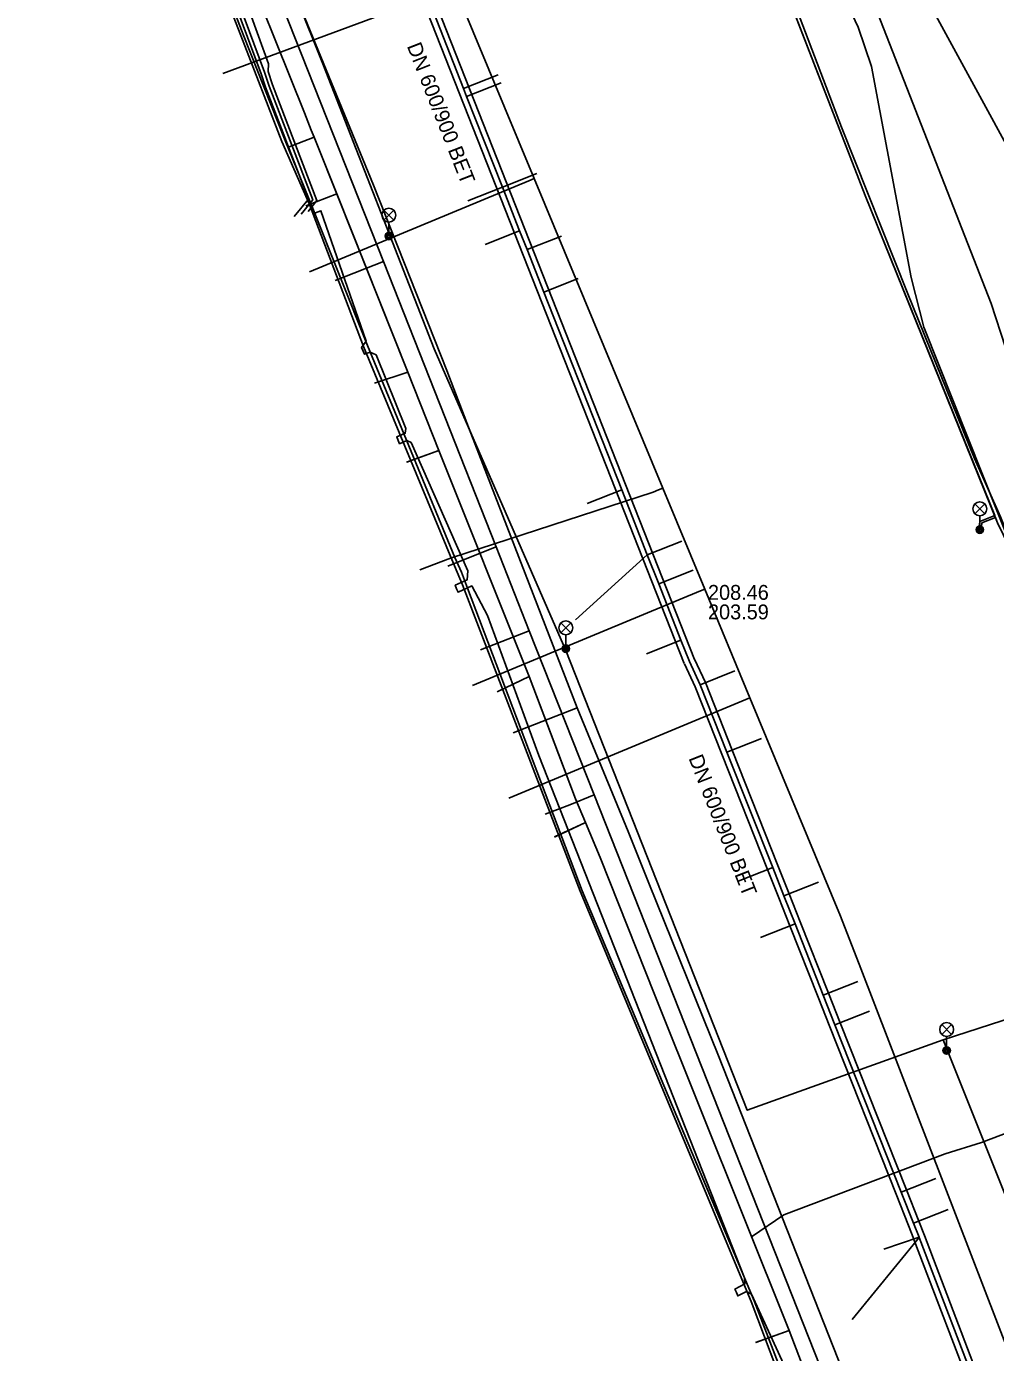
# Model space of a CAD drawing. Extents: x -595540 to -593988, y -1160850 to -1159202.
# Drawn here: x -595539.6 to -595487.4, y -1160398.9 to -1160327.6 of the extents above; entities that cross this region are included whole.
import ezdxf

# ---------------------------------------------------------------- set-up
doc = ezdxf.new("R2010")
doc.units = 0
for name, color, linetype in [('BKOM-ODVODNENI_trasa sítě', 7, 'Continuous'), ('BKOM_kabel koordinační_optický', 7, 'Continuous'), ('BVK-JEDNOTNA_popisy', 7, 'Continuous'), ('BVK-JEDNOTNA_trasa sítě', 7, 'Continuous'), ('BVK-JEDNOTNA_trasa sítě obvodem', 7, 'Continuous'), ('BVK-VODOVOD_trasa sítě', 7, 'Continuous'), ('CETIN_kabel podzemní', 7, 'Continuous'), ('DESTOVA_trasa neprovozované sítě', 7, 'Continuous'), ('DSP-SDEL-VODAFONE_kabel', 7, 'Continuous'), ('EON-NN_kabel', 7, 'Continuous'), ('EON-VN_kabel', 7, 'Continuous'), ('INNOGY-NTL_trasa sítě', 7, 'Continuous'), ('JEDNOTNA_trasa neprovozované sítě', 7, 'Continuous'), ('QUANTCOM_kabel', 7, 'Continuous'), ('TSB_kabel VO', 7, 'Continuous'), ('TSB_lampy VO', 7, 'Continuous')]:
    doc.layers.add(name, color=color, linetype=linetype)

msp = doc.modelspace()

# ---------------------------------------------------------------- linework, layer by layer
at = {"layer": 'BKOM-ODVODNENI_trasa sítě'}
msp.add_lwpolyline([(-595475.09, -1160355.55), (-595496.29, -1160316.63)], dxfattribs=at)
at = {"layer": 'BKOM_kabel koordinační_optický'}
msp.add_lwpolyline([(-595453.88, -1160433.69), (-595454.28, -1160431.7), (-595454.73, -1160428.35), (-595462.77, -1160409.14), (-595463.73, -1160407.01), (-595469.51, -1160393.32), (-595469.87, -1160391.31), (-595471.08, -1160389.95), (-595477.1, -1160376.11), (-595482.21, -1160364.84), (-595487.33, -1160354.29), (-595494.46, -1160336.67), (-595499.2, -1160324.44), (-595503.07, -1160314.66), (-595503, -1160311.72), (-595511.85, -1160289.79), (-595512.776, -1160289.263), (-595513.395, -1160289.497), (-595514.12, -1160290.65), (-595514.78, -1160289.19), (-595513.85, -1160288.56)], dxfattribs=at)
at = {"layer": 'BVK-JEDNOTNA_popisy'}
msp.add_line((-595502.914, -1160358.559), (-595502.914, -1160358.559), dxfattribs=at)
at = {"layer": 'BVK-JEDNOTNA_trasa sítě'}
for points in [[(-595503.914, -1160361.759), (-595504.369, -1160360.605), (-595505.564, -1160357.572), (-595506.18, -1160356.009), (-595507.555, -1160352.52), (-595511.753, -1160341.867), (-595512.651, -1160339.588), (-595513.047, -1160338.583), (-595513.975, -1160336.229), (-595515.904, -1160331.336), (-595516.073, -1160330.908), (-595517.51, -1160327.261), (-595518.002, -1160326.012), (-595520.106, -1160320.768)], [(-595488.167, -1160401.618), (-595491.55, -1160392.753), (-595491.553, -1160392.744), (-595491.851, -1160391.991), (-595492.518, -1160390.308), (-595496.082, -1160381.308), (-595496.715, -1160379.709), (-595498.232, -1160375.878), (-595498.828, -1160374.372), (-595499.432, -1160372.847), (-595501.895, -1160366.627), (-595503.331, -1160363.001), (-595503.914, -1160361.759)]]:
    msp.add_lwpolyline(points, dxfattribs=at)
at = {"layer": 'BVK-JEDNOTNA_trasa sítě obvodem'}
for points in [[(-595504.193, -1160361.869), (-595518.281, -1160326.123), (-595520.385, -1160320.88)], [(-595519.828, -1160320.656), (-595517.723, -1160325.901), (-595503.635, -1160361.649)], [(-595503.642, -1160361.632), (-595503.055, -1160362.882), (-595501.616, -1160366.517), (-595499.153, -1160372.737), (-595498.549, -1160374.262), (-595497.953, -1160375.768), (-595496.436, -1160379.599), (-595495.803, -1160381.198), (-595492.239, -1160390.198), (-595491.572, -1160391.88), (-595491.271, -1160392.641), (-595491.267, -1160392.652), (-595487.887, -1160401.511)], [(-595488.448, -1160401.724), (-595491.833, -1160392.854), (-595491.835, -1160392.847), (-595492.13, -1160392.101), (-595492.797, -1160390.419), (-595496.361, -1160381.418), (-595496.994, -1160379.819), (-595498.511, -1160375.988), (-595499.107, -1160374.482), (-595499.711, -1160372.957), (-595502.174, -1160366.737), (-595503.607, -1160363.12), (-595504.186, -1160361.886)]]:
    msp.add_lwpolyline(points, dxfattribs=at)
at = {"layer": 'BVK-VODOVOD_trasa sítě'}
for points in [[(-595420.455, -1160569.95), (-595424.738, -1160557.073), (-595431.327, -1160540.422), (-595434.589, -1160532.179), (-595436.214, -1160528.074), (-595442.962, -1160511.021), (-595456.206, -1160477.553), (-595459.57, -1160469.052), (-595464.421, -1160456.794), (-595465.595, -1160453.828), (-595470.116, -1160442.088), (-595472.995, -1160434.855), (-595482.155, -1160410.824), (-595494.687, -1160378.28), (-595495.79, -1160375.461), (-595500.663, -1160363.717), (-595503.091, -1160357.865), (-595505.35, -1160352.422), (-595512.262, -1160335.764), (-595517.983, -1160321.988), (-595525.805, -1160303.126), (-595529.181, -1160294.991), (-595529.357, -1160294.499)], [(-595512.262, -1160335.764), (-595512.546, -1160335.882), (-595524.354, -1160340.782)], [(-595505.35, -1160352.422), (-595505.582, -1160352.518), (-595505.858, -1160352.632), (-595516.77, -1160356.193), (-595518.424, -1160356.822)], [(-595503.091, -1160357.865), (-595503.313, -1160357.957), (-595515.592, -1160363.052)], [(-595500.663, -1160363.717), (-595501.094, -1160363.896), (-595513.633, -1160369.104)]]:
    msp.add_lwpolyline(points, dxfattribs=at)
at = {"layer": 'CETIN_kabel podzemní'}
for points in [[(-595535.44, -1160304.73), (-595532.73, -1160311.57), (-595528.44, -1160322.69), (-595524.63, -1160332.22), (-595524.26, -1160333.15), (-595524.11, -1160333.54)], [(-595530.4, -1160311.78), (-595527.16, -1160320.89), (-595520.91, -1160336.12), (-595516.97, -1160346.1), (-595515.89, -1160348.9), (-595509.95, -1160364.24)], [(-595524.11, -1160333.54), (-595523.89, -1160334.08), (-595522.89, -1160336.58)], [(-595522.89, -1160336.58), (-595524.56, -1160337.23)], [(-595522.89, -1160336.58), (-595519.06, -1160346.19)], [(-595519.06, -1160346.19), (-595520.8, -1160346.76)], [(-595519.06, -1160346.19), (-595517.4, -1160350.4)], [(-595517.4, -1160350.4), (-595519.12, -1160351.02)], [(-595517.4, -1160350.4), (-595512.53, -1160362.57)], [(-595512.53, -1160362.57), (-595514.26, -1160363.38)], [(-595512.53, -1160362.57), (-595510.96, -1160366.72)], [(-595509.95, -1160364.24), (-595513.39, -1160365.6)], [(-595509.95, -1160364.24), (-595507.21, -1160370.91), (-595506.09, -1160373.69), (-595502.35, -1160382.98), (-595492.49, -1160408.01)], [(-595510.96, -1160366.72), (-595510.05, -1160369.15), (-595509.51, -1160370.42)], [(-595509.51, -1160370.42), (-595511.18, -1160371.2)], [(-595509.51, -1160370.42), (-595508.72, -1160372.3), (-595505.77, -1160379.71), (-595498.55, -1160397.76)], [(-595498.55, -1160397.76), (-595500.34, -1160398.41)], [(-595498.55, -1160397.76), (-595494.66, -1160407.96)]]:
    msp.add_lwpolyline(points, dxfattribs=at)
at = {"layer": 'DESTOVA_trasa neprovozované sítě'}
for p, q in [((-595510.05, -1160359.51), (-595506.18, -1160356.009)), ((-595495.16, -1160397.17), (-595491.55, -1160392.753))]:
    msp.add_line(p, q, dxfattribs=at)
at = {"layer": 'DSP-SDEL-VODAFONE_kabel'}
msp.add_line((-595525.54, -1160334.09), (-595524.11, -1160333.54), dxfattribs=at)
for points in [[(-595435.305, -1160474.248), (-595440.905, -1160460.593), (-595441.624, -1160459.06), (-595443.903, -1160453.407), (-595444.463, -1160451.965), (-595447.439, -1160442.87), (-595449.5, -1160437.934), (-595451.793, -1160431.633), (-595454.837, -1160425.072), (-595456.717, -1160421.092), (-595460.193, -1160411.285), (-595468.387, -1160391.375), (-595474.605, -1160375.018), (-595475.298, -1160372.796), (-595476.233, -1160371.486), (-595479.459, -1160363.137), (-595482.711, -1160354.568), (-595483.438, -1160353.548), (-595486.91, -1160344.849), (-595487.674, -1160342.479), (-595505.065, -1160298.01)], [(-595435.305, -1160474.248), (-595440.905, -1160460.593), (-595441.624, -1160459.06), (-595443.903, -1160453.407), (-595444.463, -1160451.965), (-595447.439, -1160442.87), (-595449.5, -1160437.934), (-595451.793, -1160431.633), (-595454.837, -1160425.072), (-595456.717, -1160421.092), (-595460.193, -1160411.285), (-595468.387, -1160391.375), (-595474.605, -1160375.018), (-595475.298, -1160372.796), (-595476.233, -1160371.486), (-595479.459, -1160363.137), (-595482.711, -1160354.568), (-595483.438, -1160353.548), (-595486.91, -1160344.849), (-595487.674, -1160342.479), (-595505.065, -1160298.01)], [(-595435.305, -1160474.248), (-595440.905, -1160460.593), (-595441.624, -1160459.06), (-595443.903, -1160453.407), (-595444.463, -1160451.965), (-595447.439, -1160442.87), (-595449.5, -1160437.934), (-595451.793, -1160431.633), (-595454.837, -1160425.072), (-595456.717, -1160421.092), (-595460.193, -1160411.285), (-595468.387, -1160391.375), (-595474.605, -1160375.018), (-595475.298, -1160372.796), (-595476.233, -1160371.486), (-595479.459, -1160363.137), (-595482.711, -1160354.568), (-595483.438, -1160353.548), (-595486.91, -1160344.849), (-595487.674, -1160342.479), (-595505.065, -1160298.01)], [(-595535.44, -1160304.73), (-595532.73, -1160311.57), (-595528.44, -1160322.69), (-595524.63, -1160332.22), (-595524.26, -1160333.15), (-595524.11, -1160333.54)], [(-595524.11, -1160333.54), (-595523.89, -1160334.08), (-595519.06, -1160346.19)], [(-595519.06, -1160346.19), (-595520.86, -1160346.78)], [(-595519.06, -1160346.19), (-595517.4, -1160350.4)], [(-595517.4, -1160350.4), (-595519.14, -1160351.02)], [(-595517.4, -1160350.4), (-595512.53, -1160362.57)], [(-595512.53, -1160362.57), (-595514.23, -1160363.37)], [(-595512.53, -1160362.57), (-595510.05, -1160369.15), (-595509.51, -1160370.42)], [(-595509.51, -1160370.42), (-595511.17, -1160371.19)], [(-595509.51, -1160370.42), (-595508.72, -1160372.3), (-595505.77, -1160379.71), (-595498.55, -1160397.76)], [(-595500.568, -1160392.714), (-595498.836, -1160391.537), (-595490.156, -1160388.25), (-595488.199, -1160387.639), (-595477.415, -1160383.543), (-595475.296, -1160382.4), (-595473.16, -1160381.501), (-595472.348, -1160380.96)], [(-595498.55, -1160397.76), (-595500.36, -1160398.41)], [(-595498.55, -1160397.76), (-595494.66, -1160407.96), (-595494.58, -1160408.17)]]:
    msp.add_lwpolyline(points, dxfattribs=at)
at = {"layer": 'EON-NN_kabel'}
for points in [[(-595539.58, -1160304.194), (-595539.233, -1160304.113), (-595537.913, -1160303.785), (-595537.445, -1160303.569), (-595537.294, -1160303.859), (-595536.28, -1160305.807), (-595534.797, -1160309.192), (-595533.658, -1160312.2), (-595533.263, -1160312.99), (-595533.013, -1160313.371), (-595532.828, -1160313.761), (-595526.768, -1160330.041), (-595526.53, -1160330.78), (-595524.18, -1160336.9), (-595524.8, -1160337.67)], [(-595539.58, -1160305.231), (-595539.45, -1160305.082), (-595539.007, -1160304.639), (-595537.477, -1160303.943), (-595537.294, -1160303.859), (-595536.974, -1160303.714), (-595536.692, -1160303.785), (-595536.212, -1160304.556), (-595528.462, -1160324.303), (-595526.569, -1160329.588), (-595526.57, -1160329.993)], [(-595525.171, -1160337.812), (-595524.408, -1160336.864), (-595526.719, -1160330.846), (-595526.952, -1160330.119), (-595533.012, -1160313.839), (-595533.187, -1160313.469), (-595533.437, -1160313.09), (-595533.842, -1160312.28), (-595534.983, -1160309.268), (-595536.46, -1160305.893), (-595537.477, -1160303.943), (-595537.535, -1160303.831), (-595537.847, -1160303.975), (-595539.187, -1160304.307), (-595539.58, -1160304.398)], [(-595485.759, -1160357.679), (-595491.299, -1160343.751), (-595491.99, -1160341.082), (-595494.119, -1160329.738), (-595494.834, -1160327.604), (-595500.917, -1160314.761)], [(-595526.57, -1160329.993), (-595526.341, -1160330.714), (-595523.952, -1160336.936), (-595524.43, -1160337.53)], [(-595524.028, -1160337.61), (-595523.738, -1160337.497), (-595521.307, -1160344.504), (-595521.553, -1160344.857), (-595521.473, -1160345.043), (-595521.395, -1160345.219), (-595521.087, -1160345.108), (-595520.774, -1160345.256), (-595519.175, -1160349.205), (-595519.206, -1160349.467), (-595519.658, -1160349.668), (-595519.581, -1160349.853), (-595519.508, -1160350.038), (-595519.116, -1160349.863), (-595518.888, -1160349.97), (-595515.833, -1160356.882), (-595515.867, -1160357.357), (-595516.516, -1160357.651), (-595516.441, -1160357.846), (-595516.364, -1160358.023), (-595515.628, -1160357.685), (-595514.77, -1160359.278), (-595512.022, -1160366.82), (-595500.942, -1160394.926), (-595500.932, -1160395.252), (-595501.462, -1160395.529), (-595501.388, -1160395.714), (-595501.313, -1160395.899), (-595500.847, -1160395.659), (-595500.572, -1160395.809), (-595497, -1160403.581)]]:
    msp.add_lwpolyline(points, dxfattribs=at)
at = {"layer": 'EON-VN_kabel'}
for points in [[(-595539.58, -1160304.6), (-595537.39, -1160304.037), (-595537.337, -1160304.167), (-595535.294, -1160309.222), (-595532.068, -1160317.722), (-595528.053, -1160328.061), (-595525.844, -1160333.763), (-595524.361, -1160337.161), (-595521.451, -1160344.799), (-595516.694, -1160356.261), (-595516.131, -1160357.63), (-595509.796, -1160374.111), (-595500.594, -1160396.206), (-595498.49, -1160401.758), (-595496.239, -1160408.557), (-595495.543, -1160410.174), (-595494.002, -1160414.071), (-595493.496, -1160415.346), (-595489.805, -1160424.925), (-595488.92, -1160427.22), (-595488.55, -1160428.04)], [(-595536.452, -1160304.115), (-595536.948, -1160304.477), (-595535.17, -1160309.192), (-595531.907, -1160317.657), (-595527.932, -1160327.999), (-595525.659, -1160333.708), (-595524.206, -1160337.276), (-595521.239, -1160344.744), (-595516.526, -1160356.155), (-595516.18, -1160356.944), (-595515.853, -1160357.81), (-595509.676, -1160374.105), (-595500.429, -1160396.17), (-595498.294, -1160401.713), (-595496.04, -1160408.403), (-595495.359, -1160410.048), (-595493.893, -1160413.8), (-595493.4, -1160415.083), (-595489.578, -1160424.856), (-595487.454, -1160430.5), (-595480.445, -1160447.736), (-595470.955, -1160472.047)]]:
    msp.add_lwpolyline(points, dxfattribs=at)
at = {"layer": 'INNOGY-NTL_trasa sítě'}
for points in [[(-595536.75, -1160299.05), (-595534.05, -1160305.92), (-595529.86, -1160316.21), (-595525.781, -1160326.533), (-595520.37, -1160340.23), (-595514.31, -1160355.59), (-595512.53, -1160360.1), (-595509.04, -1160368.93), (-595495.66, -1160402.79), (-595489.69, -1160417.89), (-595489.372, -1160418.696), (-595479.78, -1160443), (-595468.14, -1160472.65), (-595465.37, -1160479.83), (-595465.284, -1160480.052), (-595451.91, -1160514.65), (-595447.47, -1160526.12), (-595442.34, -1160539.41), (-595439.6, -1160546.49), (-595433.96, -1160559.84)], [(-595520.37, -1160340.23), (-595522.97, -1160341.25)], [(-595514.31, -1160355.59), (-595516.43, -1160356.43)], [(-595516.43, -1160356.43), (-595516.92, -1160356.62)], [(-595512.53, -1160360.1), (-595515.15, -1160361.13)], [(-595509.04, -1160368.93), (-595510.35, -1160369.46), (-595511.67, -1160369.97)]]:
    msp.add_lwpolyline(points, dxfattribs=at)
at = {"layer": 'JEDNOTNA_trasa neprovozované sítě'}
for p, q in [((-595529.023, -1160330.101), (-595518.002, -1160326.012)), ((-595514.212, -1160330.175), (-595516.073, -1160330.908)), ((-595514.043, -1160330.603), (-595515.904, -1160331.336)), ((-595512.114, -1160335.495), (-595513.975, -1160336.229)), ((-595515.836, -1160336.963), (-595513.975, -1160336.229)), ((-595514.908, -1160339.316), (-595513.047, -1160338.583)), ((-595510.79, -1160338.855), (-595512.651, -1160339.588)), ((-595509.892, -1160341.134), (-595511.753, -1160341.867)), ((-595509.416, -1160353.253), (-595507.555, -1160352.52)), ((-595504.319, -1160355.276), (-595506.18, -1160356.009)), ((-595503.703, -1160356.839), (-595505.564, -1160357.572)), ((-595506.23, -1160361.338), (-595504.369, -1160360.605)), ((-595501.472, -1160362.265), (-595503.331, -1160363.001)), ((-595500.035, -1160365.891), (-595501.895, -1160366.627)), ((-595501.291, -1160373.583), (-595499.432, -1160372.847)), ((-595496.968, -1160373.636), (-595498.828, -1160374.372)), ((-595500.092, -1160376.614), (-595498.232, -1160375.878)), ((-595494.855, -1160378.973), (-595496.715, -1160379.709)), ((-595494.222, -1160380.572), (-595496.082, -1160381.308)), ((-595490.659, -1160389.571), (-595492.518, -1160390.308)), ((-595489.991, -1160391.255), (-595491.851, -1160391.991)), ((-595493.45, -1160393.376), (-595491.553, -1160392.744))]:
    msp.add_line(p, q, dxfattribs=at)
at = {"layer": 'QUANTCOM_kabel'}
msp.add_lwpolyline([(-595499.12, -1160324.06), (-595495.73, -1160332.99), (-595492.17, -1160341.96), (-595488.57, -1160350.83), (-595487.18, -1160353.97), (-595486.86, -1160354.77), (-595481.25, -1160363.46), (-595476.78, -1160370.84), (-595474.59, -1160374.56), (-595465.72, -1160396.67), (-595460.95, -1160408.7), (-595460.33, -1160410.5), (-595459.72, -1160412.42)], dxfattribs=at)
at = {"layer": 'TSB_kabel VO'}
for points in [[(-595531.83, -1160309.236), (-595530.75, -1160311.8), (-595523.64, -1160329.58), (-595520.05, -1160338.774)], [(-595499.176, -1160324.493), (-595494.458, -1160336.667), (-595487.489, -1160353.89), (-595488.283, -1160354.211), (-595488.327, -1160354.504), (-595488.29, -1160354.66), (-595488.205, -1160354.498), (-595488.174, -1160354.296), (-595487.444, -1160354.001), (-595487.328, -1160354.287), (-595482.208, -1160364.837), (-595478.09, -1160373.92), (-595475.888, -1160372.871)], [(-595520.05, -1160338.774), (-595517.65, -1160344.92), (-595510.561, -1160361.167), (-595500.8, -1160385.91), (-595490.26, -1160382.12), (-595479.46, -1160378.61), (-595477.328, -1160377.573), (-595475.888, -1160372.871)], [(-595475.888, -1160372.871), (-595477.322, -1160377.57), (-595479.46, -1160378.61), (-595490.26, -1160382.12), (-595470.48, -1160431.58), (-595465.993, -1160443.276), (-595449.904, -1160483.964), (-595447.55, -1160489.04), (-595433.665, -1160524.876), (-595425.09, -1160546.12), (-595416.386, -1160566.271), (-595409.37, -1160581.87), (-595404.88, -1160593.47), (-595398.89, -1160612.37), (-595394.888, -1160630.669), (-595381.85, -1160627.34), (-595377.55, -1160645.69), (-595370.81, -1160681.62), (-595368, -1160707.44), (-595363.14, -1160706.51), (-595357.289, -1160726.656), (-595356.615, -1160726.463)]]:
    msp.add_lwpolyline(points, dxfattribs=at)
at = {"layer": 'TSB_lampy VO'}
for p, q in [((-595520.354, -1160337.995), (-595519.824, -1160337.465)), ((-595520.354, -1160337.465), (-595519.824, -1160337.995)), ((-595520.354, -1160337.995), (-595519.824, -1160337.465)), ((-595520.354, -1160337.465), (-595519.824, -1160337.995)), ((-595520.089, -1160338.105), (-595520.089, -1160338.855)), ((-595520.089, -1160338.105), (-595520.089, -1160338.855)), ((-595488.555, -1160353.8), (-595488.025, -1160353.27)), ((-595488.555, -1160353.27), (-595488.025, -1160353.8)), ((-595488.555, -1160353.8), (-595488.025, -1160353.27)), ((-595488.555, -1160353.27), (-595488.025, -1160353.8)), ((-595488.29, -1160353.91), (-595488.29, -1160354.66)), ((-595488.29, -1160353.91), (-595488.29, -1160354.66)), ((-595510.826, -1160360.204), (-595510.296, -1160359.674)), ((-595510.826, -1160359.674), (-595510.296, -1160360.204)), ((-595510.826, -1160360.204), (-595510.296, -1160359.674)), ((-595510.826, -1160359.674), (-595510.296, -1160360.204)), ((-595510.561, -1160360.314), (-595510.561, -1160361.064)), ((-595510.561, -1160360.314), (-595510.561, -1160361.064)), ((-595490.337, -1160381.828), (-595489.807, -1160381.298)), ((-595490.337, -1160381.298), (-595489.807, -1160381.828)), ((-595490.337, -1160381.828), (-595489.807, -1160381.298)), ((-595490.337, -1160381.298), (-595489.807, -1160381.828)), ((-595490.072, -1160381.938), (-595490.072, -1160382.688)), ((-595490.072, -1160381.938), (-595490.072, -1160382.688))]:
    msp.add_line(p, q, dxfattribs=at)
for centre, radius in [((-595520.089, -1160337.73), 0.375), ((-595520.089, -1160337.73), 0.375), ((-595520.089, -1160338.855), 0.2), ((-595520.089, -1160338.855), 0.2), ((-595520.089, -1160338.855), 0.145), ((-595520.089, -1160338.855), 0.145), ((-595520.089, -1160338.855), 0.0876), ((-595520.089, -1160338.855), 0.0876), ((-595488.29, -1160353.535), 0.375), ((-595488.29, -1160353.535), 0.375), ((-595488.29, -1160354.66), 0.2), ((-595488.29, -1160354.66), 0.2), ((-595488.29, -1160354.66), 0.145), ((-595488.29, -1160354.66), 0.145), ((-595488.29, -1160354.66), 0.0876), ((-595488.29, -1160354.66), 0.0876), ((-595510.561, -1160359.939), 0.375), ((-595510.561, -1160359.939), 0.375), ((-595510.561, -1160361.064), 0.2), ((-595510.561, -1160361.064), 0.2), ((-595510.561, -1160361.064), 0.145), ((-595510.561, -1160361.064), 0.145), ((-595510.561, -1160361.064), 0.0876), ((-595510.561, -1160361.064), 0.0876), ((-595490.072, -1160381.563), 0.375), ((-595490.072, -1160381.563), 0.375), ((-595490.072, -1160382.688), 0.2), ((-595490.072, -1160382.688), 0.2), ((-595490.072, -1160382.688), 0.145), ((-595490.072, -1160382.688), 0.145), ((-595490.072, -1160382.688), 0.0876), ((-595490.072, -1160382.688), 0.0876)]:
    msp.add_circle(centre, radius, dxfattribs=at)

# ---------------------------------------------------------------- texts
at = {"layer": 'BVK-JEDNOTNA_popisy'}
for rotation, p in [(291.50887, (-595519.126, -1160328.625)), (291.57822, (-595503.973, -1160366.953))]:
    msp.add_text('DN 600/900 BET', height=0.8, rotation=rotation, dxfattribs=at).set_placement(p)
for s, p in [('208.46', (-595502.914, -1160358.434)), ('203.59', (-595502.914, -1160359.484))]:
    msp.add_text(s, height=0.8, dxfattribs=at).set_placement(p)

doc.saveas('drawing.dxf')
